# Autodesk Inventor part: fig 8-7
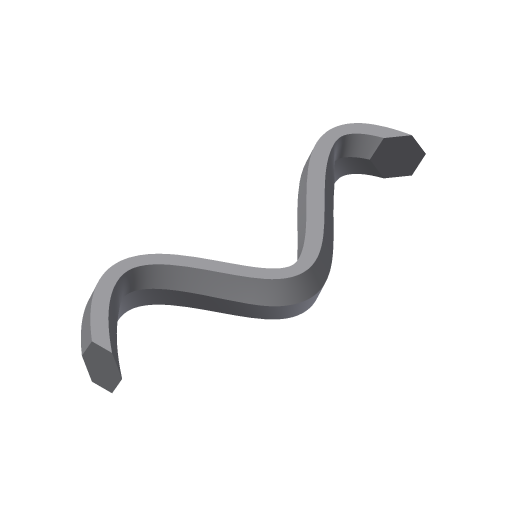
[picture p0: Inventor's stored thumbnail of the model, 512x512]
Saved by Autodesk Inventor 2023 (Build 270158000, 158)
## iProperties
Created: 2006-01
Part Number: fig 8-7
Document SubType Name: Modeling
Designer: CADCIM
Density: 1 g/cm^3
Material: Generic
Appearance: Default
Author: CADCIM
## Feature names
1. Sweep4
## Parameters: d3 = 0, d4 = 0
